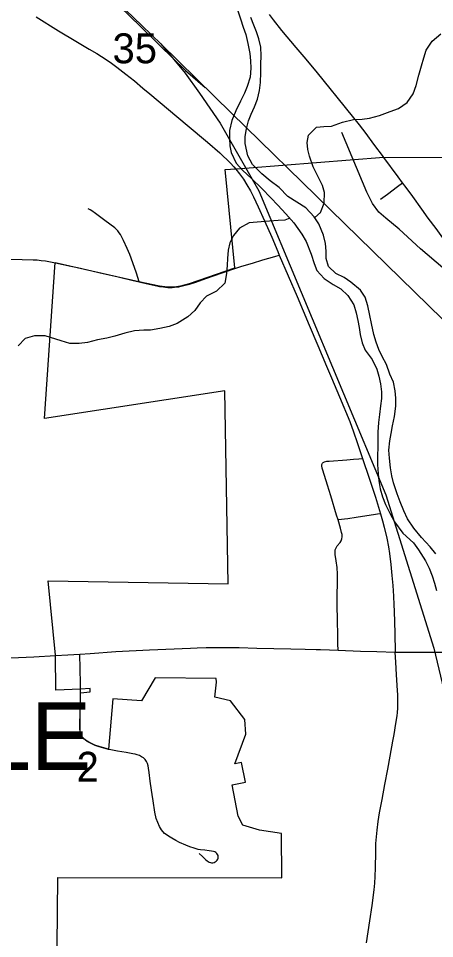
# Model space of a CAD drawing. Extents: x -7.5 to 53.5, y 0 to 22.
# Drawn here: x 3.008 to 3.591, y 16.532 to 17.82 of the extents above; entities that cross this region are included whole.
import ezdxf

# ---------------------------------------------------------------- set-up
doc = ezdxf.new("R2010")
doc.units = 0
for name, color, linetype in [('GM_X_City_Street', 7, 'Continuous'), ('GM_X_Corporation', 7, 'Continuous'), ('GM_X_Corporation_Text', 7, 'Continuous'), ('GM_X_County_Road', 7, 'Continuous'), ('GM_X_Major_River', 7, 'Continuous'), ('GM_X_Minor_River', 7, 'Continuous'), ('GM_X_Rail_Line', 7, 'Continuous'), ('GM_X_Section_Text', 7, 'Continuous'), ('GM_X_State_Route', 7, 'Continuous'), ('GM_X_Township_Road', 7, 'Continuous')]:
    doc.layers.add(name, color=color, linetype=linetype)

msp = doc.modelspace()

# ---------------------------------------------------------------- linework, layer by layer
at = {"layer": 'GM_X_City_Street'}
for points in [[(3.5156, 17.567), (3.5255, 17.5742), (3.5396, 17.5849), (3.5466, 17.5901)], [(3.5158, 17.1268), (3.5112, 17.1261), (3.5084, 17.1257), (3.4817, 17.1216), (3.4698, 17.1199), (3.4563, 17.1184), (3.4542, 17.1249), (3.4461, 17.1519), (3.4416, 17.1669), (3.4348, 17.1878), (3.434, 17.1908), (3.4333, 17.1941), (3.4334, 17.196), (3.4343, 17.1976), (3.4355, 17.1988), (3.4373, 17.1996), (3.4406, 17.2003), (3.4436, 17.2005), (3.4684, 17.2024), (3.4778, 17.2033), (3.4852, 17.2039), (3.4906, 17.2044)], [(3.4556, 17.0365), (3.4555, 17.0425), (3.4547, 17.0517), (3.4535, 17.0608), (3.4521, 17.0699), (3.4519, 17.0731), (3.4522, 17.0763), (3.4533, 17.0794), (3.4551, 17.0821), (3.4591, 17.0868), (3.4606, 17.0892), (3.4615, 17.0919), (3.4618, 17.0948), (3.4617, 17.0977), (3.4612, 17.1006), (3.4597, 17.1065), (3.4563, 17.1184)], [(3.4562, 16.936), (3.456, 16.9446), (3.4557, 16.9558), (3.4552, 16.9785), (3.4549, 16.9986), (3.455, 17.0141), (3.4553, 17.0295), (3.4556, 17.0365)], [(3.496, 16.5265), (3.5006, 16.5573), (3.5038, 16.5788), (3.5066, 16.6005), (3.5075, 16.6098), (3.5082, 16.6191), (3.5087, 16.6315), (3.509, 16.6532), (3.5093, 16.6656), (3.5099, 16.6749), (3.5108, 16.6841), (3.5124, 16.6963), (3.5144, 16.7085), (3.5178, 16.7268), (3.5218, 16.748), (3.5259, 16.7693), (3.5291, 16.7875), (3.5329, 16.8088), (3.5346, 16.8179), (3.5373, 16.8332), (3.5391, 16.8442), (3.5395, 16.8486), (3.5398, 16.8549), (3.5399, 16.8611), (3.5398, 16.8736), (3.5396, 16.8797), (3.5381, 16.9013), (3.5372, 16.9191), (3.5363, 16.9332)]]:
    msp.add_lwpolyline(points, dxfattribs=at)
at = {"layer": 'GM_X_Corporation'}
msp.add_lwpolyline([(3.0578, 15.9924), (3.0636, 16.6178), (3.3776, 16.6172), (3.3768, 16.6792), (3.3462, 16.6841), (3.3226, 16.6909), (3.3164, 16.7036), (3.3079, 16.7473), (3.3265, 16.751), (3.321, 16.7788), (3.3117, 16.777), (3.3268, 16.8183), (3.3257, 16.8388), (3.3053, 16.8649), (3.2834, 16.8703), (3.286, 16.891), (3.2855, 16.8963), (3.1998, 16.8974), (3.181, 16.8649), (3.1407, 16.8678), (3.1345, 16.7976), (3.1215, 16.8011), (3.1156, 16.8031), (3.1128, 16.8043), (3.1073, 16.8071), (3.1046, 16.8086), (3.1021, 16.8104), (3.0998, 16.8124), (3.0978, 16.8146), (3.0963, 16.8171), (3.0953, 16.8198), (3.0949, 16.8227), (3.0947, 16.8258), (3.0946, 16.8319), (3.0949, 16.8485), (3.0952, 16.8761), (3.1091, 16.8776), (3.109, 16.8825), (3.0953, 16.8814), (3.061, 16.88), (3.0603, 16.9288), (3.0502, 17.0328), (3.3022, 17.0288), (3.2977, 17.2988), (3.0448, 17.2602), (3.06, 17.4785), (3.1773, 17.4522), (3.2059, 17.4458), (3.2175, 17.4443), (3.2268, 17.4445), (3.2359, 17.4459), (3.2479, 17.449), (3.3115, 17.4709), (3.2982, 17.6089), (3.3129, 17.6099), (3.3316, 17.6113), (3.5201, 17.626), (4.0682, 17.6241)], dxfattribs=at)
at = {"layer": 'GM_X_County_Road'}
for points in [[(3.4842, 17.6735), (3.4783, 17.681), (3.4667, 17.6956), (3.455, 17.7102), (3.4453, 17.7223), (3.4275, 17.7439), (3.4116, 17.7631), (3.3976, 17.7797), (3.3775, 17.8034), (3.3657, 17.8181), (3.36, 17.8258)], [(3.5197, 17.6263), (3.5065, 17.644), (3.4955, 17.659), (3.486, 17.6712), (3.4842, 17.6735)], [(3.5466, 17.5901), (3.5404, 17.5983), (3.5203, 17.6255), (3.5197, 17.6263)], [(3.6885, 17.3955), (3.6809, 17.4057), (3.6737, 17.4158), (3.6647, 17.4284), (3.6575, 17.4385), (3.6429, 17.4585), (3.63, 17.4759), (3.6097, 17.5034), (3.5934, 17.526), (3.5825, 17.5407), (3.5734, 17.5533), (3.5609, 17.571), (3.5516, 17.5834), (3.5466, 17.5901)], [(3.0946, 16.9302), (3.1089, 16.9314), (3.145, 16.934), (3.1919, 16.9365), (3.2497, 16.939), (3.259, 16.9394), (3.2714, 16.9395), (3.2806, 16.9396), (3.3176, 16.9395), (3.3422, 16.939), (3.3899, 16.9378), (3.4101, 16.9374), (3.4256, 16.937), (3.4318, 16.9368), (3.4442, 16.9364), (3.4562, 16.936)], [(2.5666, 16.9029), (2.6054, 16.9045), (2.6271, 16.9051), (2.6458, 16.9057), (2.6613, 16.9062), (2.6924, 16.9076), (2.7172, 16.9089), (2.7296, 16.9094), (2.7544, 16.9109), (2.7699, 16.9117), (2.7792, 16.9123), (2.7885, 16.9129), (2.804, 16.9139), (2.8195, 16.9149), (2.8413, 16.9162), (2.8568, 16.9172), (2.8878, 16.9189), (2.925, 16.921), (2.9714, 16.9238), (2.9962, 16.9253), (3.0085, 16.9259), (3.0302, 16.9268), (3.0605, 16.9283)], [(3.0605, 16.9283), (3.0777, 16.9294), (3.0946, 16.9302)], [(3.4562, 16.936), (3.4876, 16.9348), (3.5105, 16.9341), (3.5363, 16.9332)]]:
    msp.add_lwpolyline(points, dxfattribs=at)
at = {"layer": 'GM_X_Major_River'}
for points in [[(3.3148, 17.8338), (3.3194, 17.8198), (3.3233, 17.808), (3.3271, 17.7978), (3.3298, 17.7849), (3.3325, 17.7709), (3.3333, 17.761), (3.3338, 17.7504), (3.3331, 17.7379), (3.3289, 17.725), (3.3252, 17.7155), (3.3196, 17.7044), (3.3132, 17.6907), (3.3075, 17.6771), (3.3042, 17.6634), (3.3039, 17.652), (3.3047, 17.6418), (3.3066, 17.6323), (3.3135, 17.6175), (3.3222, 17.6077), (3.3348, 17.5963), (3.3493, 17.5823), (3.3618, 17.5691), (3.3717, 17.5589), (3.3831, 17.5468), (3.3942, 17.5343), (3.4056, 17.5184), (3.4113, 17.5078), (3.4186, 17.4904), (3.4228, 17.4771), (3.4263, 17.4673), (3.4366, 17.4563), (3.4491, 17.448), (3.4601, 17.4416), (3.47, 17.4325), (3.4784, 17.4193), (3.4815, 17.4083), (3.4838, 17.3973), (3.4858, 17.3874), (3.4873, 17.3779), (3.49, 17.3662), (3.4942, 17.356), (3.5041, 17.3427), (3.5106, 17.3295), (3.5133, 17.3196), (3.5156, 17.3086), (3.5172, 17.2976), (3.5169, 17.2881), (3.5158, 17.2779), (3.5143, 17.2657), (3.5128, 17.2547), (3.5121, 17.241), (3.5118, 17.2316), (3.5119, 17.2187), (3.5115, 17.2092), (3.5116, 17.1959), (3.5124, 17.183), (3.5132, 17.1731), (3.5151, 17.1617), (3.5182, 17.1507), (3.5228, 17.1398), (3.5285, 17.1276), (3.5354, 17.1155), (3.5469, 17.0996), (3.5617, 17.086), (3.5689, 17.0762), (3.5788, 17.061), (3.5838, 17.0508)], [(3.5532, 17.1198), (3.5482, 17.1311), (3.5433, 17.1436), (3.539, 17.155), (3.534, 17.1702), (3.5317, 17.18), (3.5294, 17.1914), (3.5282, 17.2047), (3.5274, 17.2161), (3.5285, 17.229), (3.5307, 17.2392), (3.5326, 17.2498), (3.5352, 17.2628), (3.537, 17.2776), (3.5373, 17.2886), (3.5362, 17.2988), (3.5338, 17.3113), (3.5289, 17.3223), (3.5239, 17.3356), (3.5178, 17.3469), (3.5135, 17.3568), (3.5097, 17.367), (3.5063, 17.3776), (3.5032, 17.3932), (3.5005, 17.4042), (3.4978, 17.4178), (3.4943, 17.43), (3.4874, 17.4398), (3.4741, 17.4511), (3.4646, 17.4576), (3.4532, 17.4632), (3.4429, 17.473), (3.4395, 17.4844), (3.4394, 17.4946), (3.4386, 17.5053), (3.4356, 17.5166), (3.4291, 17.5326), (3.4229, 17.5424), (3.4111, 17.5553), (3.3986, 17.5628), (3.3857, 17.5711), (3.3735, 17.5836), (3.3613, 17.593), (3.3492, 17.6028), (3.3362, 17.6157), (3.3297, 17.6278), (3.3259, 17.6449), (3.3262, 17.6547), (3.3277, 17.6657), (3.3307, 17.6768), (3.3344, 17.6863), (3.3389, 17.6965), (3.3434, 17.7072), (3.346, 17.7193), (3.3475, 17.7303), (3.3482, 17.7444), (3.3481, 17.7561), (3.3485, 17.7679), (3.348, 17.7801), (3.3453, 17.7914), (3.3419, 17.8013), (3.3381, 17.8108), (3.3338, 17.8217)], [(3.5932, 17.071), (3.5852, 17.0808), (3.573, 17.0937), (3.5624, 17.1065), (3.5532, 17.1198)], [(3.5838, 17.0508), (3.588, 17.0398), (3.5911, 17.0296), (3.5942, 17.0197)]]:
    msp.add_lwpolyline(points, dxfattribs=at)
at = {"layer": 'GM_X_Minor_River'}
for points in [[(3.4235, 17.5415), (3.4316, 17.5485), (3.4369, 17.5614), (3.4372, 17.5766), (3.4345, 17.5865), (3.4265, 17.6024), (3.4215, 17.6126), (3.4161, 17.6274), (3.4138, 17.6369), (3.413, 17.6463), (3.4149, 17.657), (3.4258, 17.668), (3.4361, 17.6688), (3.447, 17.6696), (3.4622, 17.675), (3.4777, 17.6785), (3.4898, 17.6793), (3.5, 17.6808), (3.5144, 17.6843), (3.5292, 17.6897), (3.5409, 17.6939), (3.553, 17.7027), (3.5613, 17.7145), (3.5658, 17.7262), (3.5695, 17.7407), (3.5729, 17.754), (3.5762, 17.765), (3.5796, 17.7756), (3.5879, 17.7882), (3.6, 17.7988)], [(3.3887, 17.5405), (3.3817, 17.5377), (3.3722, 17.5373), (3.3601, 17.5365), (3.3483, 17.5357), (3.3316, 17.5341), (3.318, 17.5268), (3.3097, 17.5165), (3.3045, 17.5059), (3.3023, 17.4956), (3.3012, 17.4843), (3.3008, 17.4748), (3.3001, 17.463), (3.2975, 17.4497), (3.2858, 17.4383), (3.2718, 17.4314), (3.2632, 17.4219), (3.2556, 17.4116), (3.2458, 17.4025), (3.2307, 17.3933), (3.2197, 17.3891), (3.2065, 17.3864), (3.1936, 17.384), (3.1841, 17.384), (3.1712, 17.3828), (3.1576, 17.3797), (3.1436, 17.3755), (3.1322, 17.3728), (3.1194, 17.3701), (3.105, 17.3666), (3.0936, 17.3651), (3.0807, 17.3654), (3.0682, 17.3691), (3.046, 17.3757)], [(3.046, 17.3757), (3.0308, 17.3761), (3.0179, 17.3723), (3.008, 17.362)]]:
    msp.add_lwpolyline(points, dxfattribs=at)
at = {"layer": 'GM_X_Rail_Line'}
for points in [[(3.1356, 17.8517), (3.1794, 17.8087), (3.2067, 17.7824), (3.2427, 17.7471), (3.2702, 17.7234)], [(3.1372, 17.8534), (3.1811, 17.8104), (3.2083, 17.7841), (3.3067, 17.6878), (3.4458, 17.5525), (3.6025, 17.3993)], [(3.2081, 17.7847), (3.2418, 17.7434), (3.2623, 17.7157), (3.291, 17.6735), (3.3451, 17.5787), (3.5229, 17.1533), (3.5905, 16.9386), (3.633, 16.7607), (3.7064, 16.4339), (3.7141, 16.341), (3.7047, 16.2861), (3.6889, 16.2462), (3.6625, 16.2061), (3.6262, 16.1639), (3.3846, 15.9423), (3.2658, 15.8286), (3.0899, 15.67), (3.0475, 15.6167), (3.0184, 15.5677), (2.9253, 15.4046), (2.9035, 15.3511), (2.8997, 15.3022), (2.9073, 15.2631)], [(3.7803, 17.2249), (3.7505, 17.2602), (3.7362, 17.2788), (3.7223, 17.302), (3.627, 17.4469), (3.603, 17.4711), (3.5718, 17.4976), (3.5417, 17.5251), (3.5229, 17.5407), (3.5135, 17.5489), (3.5045, 17.5612), (3.4966, 17.5772), (3.4615, 17.6604)]]:
    msp.add_lwpolyline(points, dxfattribs=at)
at = {"layer": 'GM_X_State_Route'}
for points in [[(3.0331, 17.8225), (3.0648, 17.8029), (3.0887, 17.7884), (3.1074, 17.7773), (3.1181, 17.7709), (3.1312, 17.7626), (3.139, 17.7574), (3.1465, 17.7519), (3.1588, 17.7424), (3.1709, 17.7327), (3.1829, 17.7228), (3.1924, 17.7148), (3.2185, 17.6927), (3.2447, 17.6708), (3.2733, 17.6469), (3.2906, 17.632), (3.3054, 17.6178), (3.3103, 17.6123), (3.3131, 17.6093)], [(3.3131, 17.6093), (3.318, 17.6026), (3.3235, 17.595), (3.3285, 17.5871), (3.3333, 17.579), (3.3376, 17.5707), (3.3442, 17.5566), (3.3531, 17.5367), (3.3632, 17.514), (3.3718, 17.4939), (3.3739, 17.4888), (3.3987, 17.431), (3.4155, 17.3908), (3.4278, 17.3622), (3.4402, 17.3337), (3.4472, 17.3172)], [(3.4472, 17.3172), (3.4583, 17.2906), (3.4725, 17.2561), (3.478, 17.2415), (3.4831, 17.2268), (3.4906, 17.2044), (3.4999, 17.1766), (3.5085, 17.15), (3.5158, 17.1268), (3.5186, 17.1172), (3.5209, 17.1081), (3.5243, 17.0929), (3.5268, 17.0807), (3.5283, 17.0715), (3.5302, 17.056), (3.5317, 17.0405), (3.5327, 17.0264), (3.5336, 17.0116), (3.5342, 16.9995)], [(3.5342, 16.9995), (3.5346, 16.9904), (3.5359, 16.9599), (3.5363, 16.9332)], [(3.5363, 16.9332), (3.5609, 16.933), (3.599, 16.9331), (3.6011, 16.9331), (3.6228, 16.9332), (3.6662, 16.9333), (3.6817, 16.9331), (3.7034, 16.9326), (3.7068, 16.9325), (3.7344, 16.9317), (3.7494, 16.9313)]]:
    msp.add_lwpolyline(points, dxfattribs=at)
at = {"layer": 'GM_X_Township_Road'}
msp.add_line((3.0954, 16.8755), (3.0955, 16.8808), dxfattribs=at)
for points in [[(3.1775, 17.4516), (3.1756, 17.4577), (3.1737, 17.4637), (3.1687, 17.4782), (3.1644, 17.4897), (3.1608, 17.4983), (3.1558, 17.5095), (3.153, 17.515), (3.1515, 17.5177), (3.1498, 17.5202), (3.1479, 17.5227), (3.1458, 17.5249), (3.1434, 17.5269), (3.1294, 17.5372), (3.1162, 17.547), (3.1113, 17.5507), (3.1088, 17.5524), (3.1061, 17.5538)], [(2.998, 17.4832), (3.0135, 17.483), (3.029, 17.4825), (3.0346, 17.4821), (3.0403, 17.4816), (3.0462, 17.4808), (3.0534, 17.4794), (3.0602, 17.4779)], [(3.0602, 17.4779), (3.082, 17.4733), (3.0911, 17.4715), (3.1273, 17.4634), (3.1484, 17.4587), (3.1693, 17.4536), (3.1775, 17.4516)], [(3.3117, 17.4704), (3.3216, 17.4734), (3.3362, 17.4778), (3.3508, 17.4821), (3.3676, 17.487), (3.3739, 17.4888)], [(3.1775, 17.4516), (3.1873, 17.4493), (3.2024, 17.4459), (3.2061, 17.4452), (3.2085, 17.4448), (3.2146, 17.444), (3.2177, 17.4438), (3.2208, 17.4437), (3.2239, 17.4437), (3.227, 17.4439), (3.2301, 17.4443), (3.2331, 17.4447), (3.2362, 17.4453), (3.2422, 17.4468), (3.2481, 17.4484), (3.257, 17.4512), (3.2657, 17.4542), (3.2802, 17.4596), (3.3117, 17.4704)], [(3.0955, 16.8808), (3.0953, 16.8892), (3.0951, 16.9099), (3.0946, 16.9302)], [(3.1357, 16.7969), (3.1347, 16.797), (3.1217, 16.8006), (3.1158, 16.8025), (3.113, 16.8037), (3.1075, 16.8065), (3.1048, 16.8081), (3.1023, 16.8098), (3.1, 16.8118), (3.098, 16.814), (3.0965, 16.8165), (3.0955, 16.8192), (3.0951, 16.8222), (3.0949, 16.8252), (3.0948, 16.8314), (3.0951, 16.848), (3.0954, 16.8755)], [(3.2614, 16.6514), (3.2661, 16.6473), (3.2705, 16.643), (3.273, 16.6409), (3.2758, 16.6392), (3.2775, 16.6386), (3.2791, 16.6384), (3.2809, 16.6384), (3.2826, 16.6389), (3.2841, 16.6397), (3.2854, 16.6407), (3.2867, 16.6419), (3.2876, 16.6434), (3.2883, 16.645), (3.2884, 16.6469), (3.2881, 16.6488), (3.2874, 16.6502), (3.2863, 16.6516), (3.285, 16.6527), (3.2835, 16.6535), (3.2819, 16.6541), (3.2787, 16.6548), (3.2756, 16.6553), (3.2694, 16.6559), (3.2633, 16.6566), (3.2603, 16.6572), (3.2544, 16.6588), (3.2485, 16.6608), (3.2428, 16.6631), (3.2343, 16.6669), (3.2288, 16.6697), (3.2234, 16.6727), (3.2208, 16.6743), (3.2133, 16.6794), (3.209, 16.6845), (3.2059, 16.6892), (3.2037, 16.6946), (3.2016, 16.7005), (3.1996, 16.7094), (3.1973, 16.725), (3.1958, 16.734), (3.195, 16.7402), (3.1932, 16.7525), (3.1916, 16.7648), (3.1907, 16.771), (3.19, 16.7741), (3.1891, 16.7772), (3.1877, 16.7801), (3.1858, 16.7828), (3.1835, 16.7851), (3.1808, 16.7869), (3.178, 16.7884), (3.175, 16.7895), (3.1719, 16.7904), (3.1688, 16.7911), (3.1596, 16.7928), (3.1473, 16.7947), (3.1357, 16.7969)]]:
    msp.add_lwpolyline(points, dxfattribs=at)

# ---------------------------------------------------------------- texts
at = {"layer": 'GM_X_Corporation_Text'}
msp.add_text('LOUDONVILLE', height=0.094697, rotation=0, dxfattribs=at).set_placement((2.2236, 16.7683))
at = {"layer": 'GM_X_Section_Text'}
for s, height, p in [('35', 0.04186, (3.1403, 17.7574)), ('2', 0.0419, (3.0899, 16.7518))]:
    msp.add_text(s, height=height, rotation=0, dxfattribs=at).set_placement(p)

doc.saveas('drawing.dxf')
